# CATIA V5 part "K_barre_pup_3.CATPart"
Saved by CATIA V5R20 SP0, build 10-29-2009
Part number: barre_pup_3
Bounding box of the stored display mesh (mm): x -85.875 to -67.26, y -5.496 to 191.144, z -165.877 to -103.184
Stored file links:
  G:\Khaled_CFAO_2011\ST2M\ST2M_GR2\gcausse\Khaled\CAD_ThinkMotion\K_barre_pup_3.CATPart
  C:\Documents and Settings\gcausse\Bureau\video thinkmotio\assemblage_gcausse\pupitre_think.CATProduct
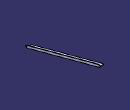
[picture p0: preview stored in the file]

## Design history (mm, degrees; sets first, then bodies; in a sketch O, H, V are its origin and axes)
Set1
  Sketch1 on Plane1, origin (-53.7378, 0, 6.6108), H (0, 1, 0), V (0.1221, 0, 0.9925)
    line L1 (187.933, -110.8457) -> (-3.7149, -168.039)
    arc A1 centre (-3, -170.4346) radius 2.5 from (-3.7149, -168.039) to (-2.2851, -172.8301) ccw
    point P3 (-3, -170.4346)
    line L2 (-2.2851, -172.8301) -> (189.3629, -115.6369)
    arc A2 centre (188.6479, -113.2413) radius 2.5 from (189.3629, -115.6369) to (187.933, -110.8457) ccw
    point P6 (188.6479, -113.2413)
    reference projected point E1 (-3, -170.4346) from Point1
    reference projected point E2 (188.6479, -113.2413) from Point2
    reference projected line E3 (-3, -170.4346) -> (188.6479, -113.2413) from Line1
    reference projected line E4 (-3, -170.4346) -> (188.6479, -113.2413) from Line1
    distance L1 L2 = 5
    tangency: A1 L1, L2 A1, A2 L2, L1 A2
    coincidence: P3 E1, P6 E2
    parallelism: L1 E3, E4 L2
Set2
  Plane1: linked copy from another document
  Point1: linked copy from another document
  Point2: linked copy from another document
  Line1: linked copy from another document
Body1 (main body)
  Pad1: profile Sketch1, direction (0.9925, 0, -0.1221), length -1
  Sketch2 on face of Pad1 from Sketch1.L2, origin (-74.8402, -2.2851, -164.9262), H (0.0349, 0.9582, 0.2838), V (-0.9925, 0, 0.1221)
    point P1 (0, 0)
    line L1 (0, 0) -> (200, 0)
    line L2 (200, 0) -> (200, 1)
    line L3 (200, 1) -> (0, 1)
    line L4 (0, 1) -> (0, 0)
    reference projected line E1 (0, 0) -> (200, 0) from Line1
    reference projected line E2 (0, 1) -> (200, 1) from edge [end face of Pad1 | face of Pad1 from Sketch1.L2]
    reference projected point E3 (200, 0) from Point2
    coincidence: P1 V, L1 E1, L3 E2, L2 E3
    horizontal: L1 H, L3 H
    vertical: L4 V
  Pad2: profile Sketch2, direction (-0.117, 0.286, -0.9511), length 1
  Sketch3 on face of Pad2, origin (-54.7303, 0, 6.7329), H (0, 1, 0), V (0.1221, 0, 0.9925)
    line L1 (189.3629, -115.6369) -> (-2.2851, -172.8301)
    line L2 (-2.2851, -172.8301) -> (-1.9991, -173.7884)
    line L3 (-1.9991, -173.7884) -> (189.6488, -116.5951)
    line L4 (189.6488, -116.5951) -> (189.3629, -115.6369)
    reference projected line E1 (189.3629, -115.6369) -> (189.6488, -116.5951) from edge [face of Pad2 from Sketch2.L2 | face of Pad2]
    reference projected line E2 (-2.2851, -172.8301) -> (-1.9991, -173.7884) from edge [face of Pad2 | face of Pad2 from Sketch2.L4]
    reference projected line E3 (189.6488, -116.5951) -> (-1.9991, -173.7884) from edge [end face of Pad2 | face of Pad2 from Sketch2.L3]
    length L2 = 1
    length L4 = 1
    coincidence: L4 E1, L2 E2, L3 E3
  Pad3: profile Sketch3, direction (-0.9925, 0, 0.1221), length 10
  Sketch4 on face of Pad2, origin (-73.7945, 47.2696, -148.2354), H (0.1221, 0, 0.9925), V (0, 1, 0)
    point P1 (-14.2981, -50.2696)
    reference projected point E1 (-14.2981, -50.2696) from Point1
    coincidence: P1 E1
  Hole1: placed by Sketch4, at (-75.5402, -3, -162.4264) direction (0.9925, 0, -0.1221), diameter 1, depth 1
  Sketch5 on face of Pad2, origin (-69.5764, 153.446, -113.9476), H (0.1221, 0, 0.9925), V (0, 1, 0)
    point P1 (8.3489, 35.2019)
    reference projected point E1 (8.3489, 35.2019) from Point2
    coincidence: P1 E1
  Hole2: placed by Sketch5, at (-68.557, 188.6479, -105.6611) direction (0.9925, 0, -0.1221), diameter 1, depth 1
